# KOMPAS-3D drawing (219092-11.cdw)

Referenced files: Кран.cdw
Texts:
  Курсова робота
  Загальний вигляд  крана КС-674
  Бабіч
  Текст на чертеже
  Размерные надписи
  Шероховатость
  Линия-выноска #1
  Линия-выноска #2
  Линия-выноска #3
  Отклонения формы и база
  Заголовок таблицы
  Ячейка таблицы
  Стрелка вида
  Обозначение изменения
  Фигурная скобка
  Номер узла
  Марка координационной оси
  VRCB
  Выносная надпись
  Обозначение узла
  Марка/позиционное обозначение с линией-выноской
  Марка/позиционное обозначение на линии
  Марка/позиционное обозначение без линии-выноски
  Q+Gвіз+Gг.о.=118,02 кН
  Тс=1,95 кН
  Тван.+Твіз.+Тг.о.=6,43 кН
  Загальний вигляд
  крана КС-674
  Горбатюк
  Курсова робота-
Dimensions and other numbers on the sheet: 7; 23100; 9000; 2800; 7500; 9300; 500; 14600; 0,5; 17,3; 19,8; 22,3; 29,1; 3,72; 3,47; -4,47; -4,72; 1,414; 1; 2; 3; 2,3; 1,8; -6,55; -6,28; -1,624; 1:200; 0; 4; 5; 6; 8; 9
